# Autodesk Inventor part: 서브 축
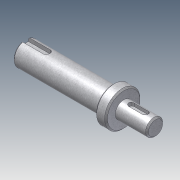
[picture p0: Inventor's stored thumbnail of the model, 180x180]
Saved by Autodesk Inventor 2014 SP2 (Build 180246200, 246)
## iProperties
Company: 한국ATC센터
Created: 2014-10
Part Number: 서브 축
Document SubType Name: Modeling
Designer: KYOUNG IL JANG
Density: 1 g/cm^3
Mass: 19.9624 g
Surface Area: 57.7178 cm^2
Volume: 19.9624 cm^3
Material: 일반
Appearance: 금속-강(스테인리스, 브러시됨)
Author: KYOUNG IL JANG
Revision Number: 1
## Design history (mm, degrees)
sketch "스케치1"
  geometry: L1 (-16.331, 0)-(-108.831, 0); L2 (-16.331, 0)-(-16.331, -6); L3 (-16.331, -6)-(-38.831, -6); L4 (-38.831, -12.5)-(-46.5, -12.5); L5 (-46.5, -8.5)-(-108.831, -8.5); L6 (-108.831, -8.5)-(-108.831, 0); L7 (-46.5, -8.5)-(-46.5, -12.5); L8 (-38.831, -6)-(-38.831, -12.5); L9 (-46.5, 12.249)-(-46.5, -12.249) reference; L10 (-38.831, -17)-(-38.831, 17) reference; 2 further points
  constraints: 17 end point, 4 perpendicular, 2 collinear, 2 parallel, 1 horizontal, 1 midpoint, 1 point on line
  dimensions: "d1" = 12 diameter of L3 L1; "d2" = 25 diameter of L4 L1; "d3" = 17 diameter of L5 L1; "d4" = 62.33128 distance of L5.start L5.end (derived); "d18" = 22.5 distance of L2.end L3.end; "d20" = 70 distance between parallel lines of L6 L8
revolve "회전1" sketch "스케치1" stored, may be unused: angle "d5" = 90 deg
chamfer "모따기1" distance "d6" = 1; stored, may be unused: second distance "d7" = 2, angle "d8" = 45 deg
node "작업 평면1"
sketch "스케치2"
  geometry: L1 (11.25, 5)-(11.25, -5) reference; L2 (-5.75, -2)-(4.25, -2); L3 (4.25, 2)-(-5.75, 2); A1 r 2 centre (4.25, 0) between (4.25, -2) and (4.25, 2); A2 r 2 centre (-5.75, 0) between (-5.75, 2) and (-5.75, -2); 2 further points
  constraints: 4 end point, 4 point on circle, 4 tangent, 2 centre point, 1 horizontal alignment, 1 midpoint, 1 parallel, 1 perpendicular
  dimensions: "d9" = 4 distance between parallel lines of L2 L3; "d10" = 14 dimension on A1 A2; "d11" = 5 distance edge to line of A1 L1
extrude "돌출1" cut sketch "스케치2" distance "d12" = 2.5; taper "d13" = 0 deg
node "작업 평면2"
sketch "스케치3"
  geometry: L1 (-31.166, -7.5)-(-31.166, 7.5) reference; L2 (-31.166, 2.5)-(-15.666, 2.5); L3 (-15.666, -2.5)-(-31.166, -2.5); A1 r 2.5 centre (-15.666, 0) between (-15.666, -2.5) and (-15.666, 2.5); 2 further points
  constraints: 4 end point, 2 perpendicular, 2 point on circle, 2 point on line, 2 tangent, 1 centre point, 1 horizontal alignment, 1 midpoint
  dimensions: "d14" = 5 distance between parallel lines of L3 L2; "d15" = 18 dimension on A1 L1
extrude "돌출2" cut sketch "스케치3" distance "d16" = 3; taper "d17" = 0 deg
node "솔리드1"
node "참조4"
node "참조5"
